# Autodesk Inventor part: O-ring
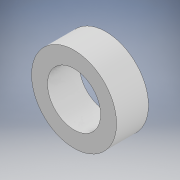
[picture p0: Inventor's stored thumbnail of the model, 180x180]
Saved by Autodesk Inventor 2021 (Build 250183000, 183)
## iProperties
Created: 2021-02
Part Number: O-ring
Material: Generic
Document SubType Name: Modeling
Designer: AHUJA
Density: 1 g/cm^3
Appearance: Default
Author: AHUJA
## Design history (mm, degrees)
sketch "Sketch1"
  geometry: C1 r 2.5 at (0, 0); C2 r 4 at (0, 0); 1 further point
  constraints: 2 centre point, 2 coincident
  dimensions: "d0" = 5 diameter of C1; "d1" = 8 diameter of C2
extrude "Extrusion1" new body sketch "Sketch1" distance "d2" = 3; taper "d3" = 0 deg
body "Solid1"
